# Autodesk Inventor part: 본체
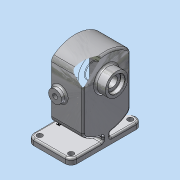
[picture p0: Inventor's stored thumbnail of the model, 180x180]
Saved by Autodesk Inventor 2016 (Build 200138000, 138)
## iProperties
Created: 2019-03
Part Number: 본체
Material: 알루미늄 6061
Document SubType Name: Modeling
Designer: Administrator
Density: 2.7 g/cm^3
Appearance: 알루미늄 - 평지
Mass: 1187.14 g
Surface Area: 719.174 cm^2
Volume: 439.681 cm^3
Author: Administrator
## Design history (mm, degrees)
sketch "스케치1"
  geometry: L1 (0, 0)-(73, 0); L2 (73, 0)-(73, 120); L3 (73, 120)-(0, 120); L4 (0, 120)-(0, 0)
  constraints: 8 end point, 2 parallel, 1 horizontal, 1 perpendicular
  dimensions: "d0" = 73 distance of L3.end L2.end; "d1" = 120 distance of L2.end L1.end
extrude "돌출1" new body sketch "스케치1" distance "d2" = 10; taper "d3" = 0 deg
sketch "스케치2"
  geometry: L1 (0, 0)-(0, 120) reference; L2 (0, 60)-(-138, 60); L3 (-138, 60)-(-138, 20); L4 (0, 0)-(-78, 0); L5 (-78, 0)-(-78, 133.922); L6 (-122.721, 20)-(-33.279, 20); L7 (-138, 60)-(-18, 60); A1 r 60 centre (-78, 60) between (-138, 60) and (-122.721, 20); A2 r 60 centre (-78, 60) between (-33.279, 20) and (-18, 60)
  constraints: 12 end point, 4 point on circle, 3 horizontal, 2 centre point, 2 symmetric about line, 2 vertical, 1 collinear, 1 midpoint, 1 other
  dimensions: "d4" = 138 distance of L2.start L2.end; "d6" = 78 distance of L1.start L4.end; "d8" = 60 radius of A1
extrude "돌출2" join sketch "스케치2" distance "d10" = 53; taper "d11" = 0 deg
sketch "스케치3"
  geometry: L1 (-53, 0)-(-53, 89.443) reference; L2 (-53, 44.721)-(0, 44.721); L3 (0, 89.443)-(0, 0) reference; C1 r 11 at (-39, 44.721); 1 further point
  constraints: 2 end point, 2 midpoint, 1 centre point, 1 point on line
  dimensions: "d12" = 22 diameter of C1; "d13" = 14 distance of C1.centre L2.start
extrude "돌출3" join sketch "스케치3" distance "d14" = 8; taper "d15" = 0 deg
node "작업 평면2"
node "작업 평면3"
sketch "스케치4"
  geometry: L1 (0, 0)-(0, 120) reference; L2 (0, 60)-(-100, 60); C1 r 19 at (-100, 60)
  constraints: 2 end point, 1 centre point, 1 coincident, 1 horizontal, 1 midpoint
  dimensions: "d19" = 100 distance of L2.start L2.end; "d21" = 38 diameter of C1
extrude "돌출4" join sketch "스케치4" distance "d22" = 17; taper "d23" = 0 deg
sketch "스케치5"
  geometry: L1 (122.721, 100)-(33.279, 100) reference; L2 (78, 100)-(78, 20); L3 (122.721, 20)-(33.279, 20) reference; L4 (100, 60)-(56, 60); L5 (100, 60)-(56, 60); L6 (100, 84)-(56, 84); L7 (56, 36)-(100, 36); A1 r 24 centre (100, 60) between (100, 36) and (100, 84); A2 r 24 centre (56, 60) between (56, 84) and (56, 36); 3 further points
  constraints: 12 end point, 5 midpoint, 4 point on circle, 4 tangent, 2 centre point, 2 equal length, 1 horizontal
  dimensions: "d24" = 44 distance of L4.start L4.end; "d25" = 24 radius of A1
extrude "돌출5" cut sketch "스케치5" distance "d26" = 29; taper "d27" = 0 deg
sketch "스케치6"
  geometry: A1 r 24 centre (100, 60) between (100, 36) and (100, 84) reference; A2 r 24 centre (56, 60) between (56, 84) and (56, 36) reference; 3 further points
  constraints: 2 coincident
hole "구멍1" sketch "스케치6" at (100, 60), (56, 60) diameter "d28" = 25; stored, may be unused: countersink angle "d32" = 90 deg, drill point angle "d34" = 0 deg; dims "d29" = 6, "d30" = 25, "d31" = 15, "d33" = 15
hole "구멍2" diameter "d37" = 17; stored, may be unused: countersink angle "d41" = 90 deg, drill point angle "d43" = 0 deg; dims "d35" = 10, "d36" = 10, "d38" = 6, "d39" = 28, "d40" = 7.3, "d42" = 15
sketch "스케치7"
  geometry: L1 (73, 0)-(73, 120) reference; L2 (73, 66)-(30, 66); L3 (30, 66)-(30, 54); L4 (30, 54)-(73, 54); L5 (73, 54)-(73, 66); 2 further points
  constraints: 8 end point, 2 midpoint, 2 parallel, 1 horizontal, 1 perpendicular, 1 point on line
  dimensions: "d44" = 12 distance between parallel lines of L4 L2; "d45" = 43 distance of L3.end L4.end
extrude "돌출6" join sketch "스케치7" stored distance "d46" = 29; taper "d47" = 0 deg
hole "구멍3" diameter "d50" = 8.376; stored, may be unused: countersink angle "d54" = 90 deg, drill point angle "d56" = 0 deg; dims "d48" = 10, "d49" = 10, "d51" = 20, "d52" = 10, "d53" = 7.3, "d55" = 27.3
fillet "모깎기1" dims "d57" = 10
sketch "스케치8"
  geometry: A1 r 10 centre (63, 110) between (73, 110) and (63, 120) reference; A2 r 10 centre (63, 10) between (63, 0) and (73, 10) reference; A3 r 10 centre (10, 10) between (0, 10) and (10, 0) reference; A4 r 10 centre (10, 110) between (10, 120) and (0, 110) reference; 5 further points
  constraints: 4 coincident
hole "구멍4" sketch "스케치8" at (63, 110), (63, 10), (10, 10), (10, 110) diameter "d58" = 9; stored, may be unused: countersink angle "d62" = 90 deg, drill point angle "d64" = 0 deg; dims "d59" = 20, "d60" = 10, "d61" = 7.3, "d63" = 27.3
fillet "모깎기2" dims "d65" = 10
sketch "스케치9"
  geometry: L1 (100, 60)-(131, 60); C1 r 8.5 at (100, 60) reference; 2 further points
  constraints: 2 end point, 1 coincident, 1 horizontal
  dimensions: "d66" = 31 distance of L1.start L1.end
hole "구멍5" sketch "스케치9" at (131, 60) diameter "d67" = 4.134; stored, may be unused: countersink angle "d71" = 90 deg, drill point angle "d73" = 118 deg; dims "d68" = 10, "d69" = 10, "d70" = 7.3, "d72" = 12
chamfer "모따기1" distance "d77" = 1; stored, may be unused: second distance "d78" = 2, angle "d79" = 45 deg
fillet "모깎기3" dims "d83" = 0.5
fillet "모깎기7" dims "d87" = 3
fillet "모깎기8" dims "d88" = 3
fillet "모깎기9" dims "d89" = 3
fillet "모깎기12" dims "d92" = 3
fillet "모깎기13" dims "d93" = 3
sketch "스케치10"
  geometry: L1 (63, 120)-(10, 120) reference; L2 (0, 110)-(0, 10) reference; 2 further points
  constraints: 1 other
  dimensions: "d94" = 60 distance from line of point (10, 60) L1; "d95" = 10 distance from line of point (10, 60) L2
feature "엠보싱1" sketch "스케치10" dims "d96" = 0.5, "d97" = 0
fillet "모깎기14" dims "d98" = 3
fillet "모깎기15" dims "d99" = 3
chamfer "모따기3" distance "d100" = 0.7; stored, may be unused: second distance "d101" = 2, angle "d102" = 30 deg
sketch "스케치11"
  geometry: L1 (60, 149.733)-(-12.774, 149.733); L2 (-12.774, 149.733)-(-12.774, 56); L3 (-12.774, 56)-(60, 56); L4 (60, 56)-(60, 149.733); 1 further point
  constraints: 8 end point, 2 parallel, 1 horizontal, 1 perpendicular
extrude "돌출7" cut sketch "스케치11" stored distance "d103" = 29; taper "d104" = 0 deg
node "솔리드1"
mirror "대칭1"
mirror "대칭2"
pattern_circular "원형 패턴1" dims angle "d75" = 180 deg
mirror "대칭3"
other parameters: "d18" = 78
